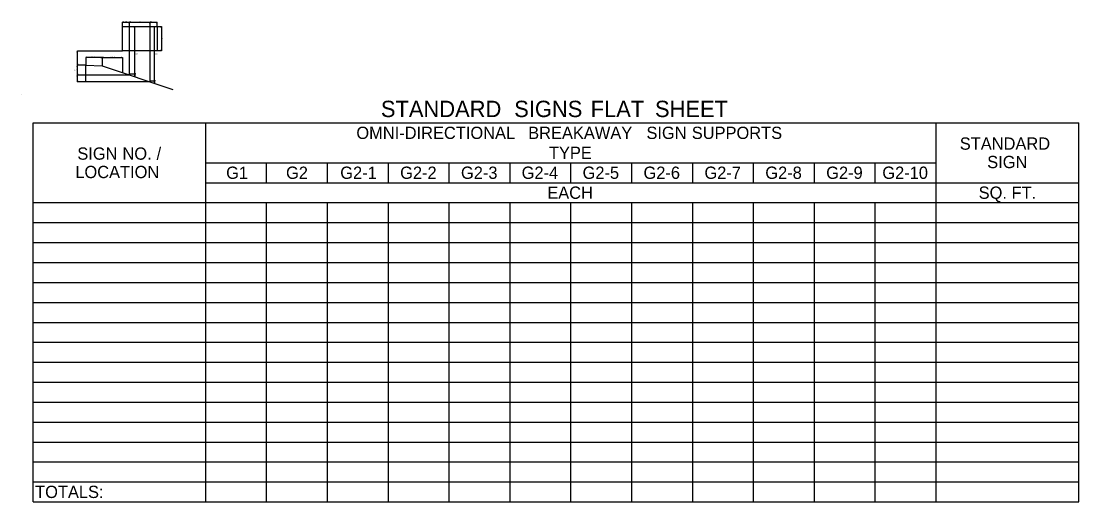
# Model space of a CAD drawing. Extents: x 229 to 4210, y 35 to 1715.
# Drawn here: x 3485 to 4002, y 1480 to 1715 of the extents above; entities that cross this region are included whole.
import ezdxf

# ---------------------------------------------------------------- set-up
doc = ezdxf.new("R2010")
doc.units = 0
for name, color, linetype in [('B_Steel', 7, 'Continuous'), ('B_Steel Hidden', 7, 'Continuous'), ('Default', 7, 'Continuous')]:
    doc.layers.add(name, color=color, linetype=linetype)

msp = doc.modelspace()

# ---------------------------------------------------------------- linework, layer by layer
at = {"layer": 'B_Steel Hidden'}
for p, q in [((3535.51, 1714.6), (3534.91, 1714.51)), ((3534.91, 1712.51), (3534.91, 1714.51)), ((3535.51, 1714.42), (3534.91, 1714.51)), ((3534.91, 1714.51), (3538.29, 1714.51)), ((3535.51, 1714.58), (3535.01, 1714.51)), ((3535.51, 1714.43), (3535.01, 1714.51)), ((3535.51, 1714.57), (3535.11, 1714.51)), ((3535.51, 1714.45), (3535.11, 1714.51)), ((3535.51, 1714.55), (3535.21, 1714.51)), ((3535.51, 1714.46), (3535.21, 1714.51)), ((3535.51, 1714.54), (3535.32, 1714.51)), ((3535.51, 1714.48), (3535.32, 1714.51)), ((3535.51, 1714.52), (3535.42, 1714.51)), ((3535.51, 1714.49), (3535.42, 1714.51)), ((3535.51, 1714.6), (3535.51, 1714.42)), ((3537.69, 1714.6), (3538.29, 1714.51)), ((3537.69, 1714.6), (3537.69, 1714.42)), ((3537.69, 1714.58), (3538.19, 1714.51)), ((3537.69, 1714.57), (3538.09, 1714.51)), ((3537.69, 1714.55), (3537.99, 1714.51)), ((3537.69, 1714.54), (3537.89, 1714.51)), ((3537.69, 1714.52), (3537.79, 1714.51)), ((3537.69, 1714.42), (3538.29, 1714.51)), ((3537.69, 1714.48), (3537.89, 1714.51)), ((3537.69, 1714.45), (3538.09, 1714.51)), ((3537.69, 1714.43), (3538.19, 1714.51)), ((3537.69, 1714.46), (3537.99, 1714.51)), ((3537.69, 1714.49), (3537.79, 1714.51)), ((3538.89, 1714.6), (3538.29, 1714.51)), ((3538.29, 1712.51), (3538.29, 1714.51)), ((3538.89, 1714.42), (3538.29, 1714.51)), ((3538.29, 1714.51), (3548.49, 1714.51)), ((3538.89, 1714.58), (3538.39, 1714.51)), ((3538.89, 1714.43), (3538.39, 1714.51)), ((3538.89, 1714.57), (3538.49, 1714.51)), ((3538.89, 1714.45), (3538.49, 1714.51)), ((3538.89, 1714.55), (3538.59, 1714.51)), ((3538.89, 1714.46), (3538.59, 1714.51)), ((3538.89, 1714.54), (3538.7, 1714.51)), ((3538.89, 1714.48), (3538.7, 1714.51)), ((3538.89, 1714.52), (3538.8, 1714.51)), ((3538.89, 1714.49), (3538.8, 1714.51)), ((3538.89, 1714.6), (3538.89, 1714.42)), ((3540.83, 1711.91), (3540.92, 1712.51)), ((3541.01, 1711.91), (3540.83, 1711.91)), ((3540.85, 1711.91), (3540.92, 1712.41)), ((3540.86, 1711.91), (3540.92, 1712.31)), ((3540.88, 1711.91), (3540.92, 1712.21)), ((3540.89, 1711.91), (3540.92, 1712.1)), ((3540.91, 1711.91), (3540.92, 1712)), ((3540.92, 1689.06), (3540.92, 1712.51)), ((3541.01, 1711.91), (3540.92, 1712.51)), ((3541, 1711.91), (3540.92, 1712.41)), ((3540.98, 1711.91), (3540.92, 1712.31)), ((3540.97, 1711.91), (3540.92, 1712.21)), ((3540.95, 1711.91), (3540.92, 1712.1)), ((3540.94, 1711.91), (3540.92, 1712)), ((3547.89, 1714.6), (3548.49, 1714.51)), ((3547.89, 1714.6), (3547.89, 1714.42)), ((3547.89, 1714.58), (3548.39, 1714.51)), ((3547.89, 1714.57), (3548.29, 1714.51)), ((3547.89, 1714.55), (3548.19, 1714.51)), ((3547.89, 1714.54), (3548.09, 1714.51)), ((3547.89, 1714.52), (3547.99, 1714.51)), ((3547.89, 1714.42), (3548.49, 1714.51)), ((3547.89, 1714.48), (3548.09, 1714.51)), ((3547.89, 1714.45), (3548.29, 1714.51)), ((3547.89, 1714.43), (3548.39, 1714.51)), ((3547.89, 1714.46), (3548.19, 1714.51)), ((3547.89, 1714.49), (3547.99, 1714.51)), ((3549.09, 1714.6), (3548.49, 1714.51)), ((3548.49, 1712.51), (3548.49, 1714.51)), ((3549.09, 1714.42), (3548.49, 1714.51)), ((3548.49, 1714.51), (3551.91, 1714.51)), ((3549.09, 1714.58), (3548.59, 1714.51)), ((3549.09, 1714.43), (3548.59, 1714.51)), ((3549.09, 1714.57), (3548.69, 1714.51)), ((3549.09, 1714.45), (3548.69, 1714.51)), ((3549.09, 1714.55), (3548.79, 1714.51)), ((3549.09, 1714.46), (3548.79, 1714.51)), ((3549.09, 1714.54), (3548.9, 1714.51)), ((3549.09, 1714.48), (3548.9, 1714.51)), ((3549.09, 1714.52), (3549, 1714.51)), ((3549.09, 1714.49), (3549, 1714.51)), ((3549.09, 1714.6), (3549.09, 1714.42)), ((3550.46, 1711.91), (3550.55, 1712.51)), ((3550.64, 1711.91), (3550.46, 1711.91)), ((3550.47, 1711.91), (3550.55, 1712.41)), ((3550.49, 1711.91), (3550.55, 1712.31)), ((3550.5, 1711.91), (3550.55, 1712.21)), ((3550.52, 1711.91), (3550.55, 1712.1)), ((3550.53, 1711.91), (3550.55, 1712)), ((3550.55, 1685.66), (3550.55, 1712.51)), ((3550.64, 1711.91), (3550.55, 1712.51)), ((3550.62, 1711.91), (3550.55, 1712.41)), ((3550.61, 1711.91), (3550.55, 1712.31)), ((3550.59, 1711.91), (3550.55, 1712.21)), ((3550.57, 1711.91), (3550.55, 1712.1)), ((3550.56, 1711.91), (3550.55, 1712)), ((3551.31, 1714.6), (3551.91, 1714.51)), ((3551.31, 1714.6), (3551.31, 1714.42)), ((3551.31, 1714.58), (3551.81, 1714.51)), ((3551.31, 1714.57), (3551.71, 1714.51)), ((3551.31, 1714.55), (3551.61, 1714.51)), ((3551.31, 1714.54), (3551.51, 1714.51)), ((3551.31, 1714.52), (3551.41, 1714.51)), ((3551.31, 1714.42), (3551.91, 1714.51)), ((3551.31, 1714.48), (3551.51, 1714.51)), ((3551.31, 1714.45), (3551.71, 1714.51)), ((3551.31, 1714.43), (3551.81, 1714.51)), ((3551.31, 1714.46), (3551.61, 1714.51)), ((3551.31, 1714.49), (3551.41, 1714.51)), ((3551.91, 1712.51), (3551.91, 1714.51)), ((3551.91, 1712.51), (3553.91, 1712.51)), ((3553.82, 1711.91), (3553.91, 1712.51)), ((3554, 1711.91), (3553.82, 1711.91)), ((3553.84, 1711.91), (3553.91, 1712.41)), ((3553.85, 1711.91), (3553.91, 1712.3)), ((3553.87, 1711.91), (3553.91, 1712.2)), ((3553.88, 1711.91), (3553.91, 1712.1)), ((3553.9, 1711.91), (3553.91, 1712)), ((3553.91, 1712.51), (3553.91, 1700.51)), ((3554, 1711.91), (3553.91, 1712.51)), ((3553.99, 1711.91), (3553.91, 1712.41)), ((3553.97, 1711.91), (3553.91, 1712.3)), ((3553.96, 1711.91), (3553.91, 1712.2)), ((3553.94, 1711.91), (3553.91, 1712.1)), ((3553.93, 1711.91), (3553.91, 1712)), ((3512.75, 1699.91), (3512.84, 1700.51)), ((3512.76, 1699.91), (3512.84, 1700.41)), ((3512.78, 1699.91), (3512.84, 1700.3)), ((3512.79, 1699.91), (3512.84, 1700.2)), ((3512.84, 1693.51), (3512.84, 1700.51)), ((3512.93, 1699.91), (3512.84, 1700.51)), ((3512.84, 1700.51), (3534.91, 1700.51)), ((3512.91, 1699.91), (3512.84, 1700.41)), ((3512.9, 1699.91), (3512.84, 1700.3)), ((3512.88, 1699.91), (3512.84, 1700.2)), ((3553.91, 1700.51), (3551.91, 1700.51)), ((3553.82, 1701.11), (3553.91, 1700.51)), ((3553.82, 1701.11), (3554, 1701.11)), ((3553.84, 1701.11), (3553.91, 1700.61)), ((3553.85, 1701.11), (3553.91, 1700.71)), ((3553.87, 1701.11), (3553.91, 1700.81)), ((3553.88, 1701.11), (3553.91, 1700.91)), ((3553.9, 1701.11), (3553.91, 1701.01)), ((3554, 1701.11), (3553.91, 1700.51)), ((3553.94, 1701.11), (3553.91, 1700.91)), ((3553.97, 1701.11), (3553.91, 1700.71)), ((3553.99, 1701.11), (3553.91, 1700.61)), ((3553.96, 1701.11), (3553.91, 1700.81)), ((3553.93, 1701.11), (3553.91, 1701.01)), ((3512.93, 1699.91), (3512.75, 1699.91)), ((3512.81, 1699.91), (3512.84, 1700.1)), ((3512.82, 1699.91), (3512.84, 1700)), ((3512.87, 1699.91), (3512.84, 1700.1)), ((3512.85, 1699.91), (3512.84, 1700)), ((3517.51, 1697.4), (3516.91, 1697.31)), ((3517.51, 1697.22), (3516.91, 1697.31)), ((3516.91, 1697.31), (3516.91, 1693.51)), ((3524.91, 1697.31), (3516.91, 1697.31)), ((3517.51, 1697.38), (3517.01, 1697.31)), ((3517.51, 1697.23), (3517.01, 1697.31)), ((3517.51, 1697.37), (3517.11, 1697.31)), ((3517.51, 1697.25), (3517.11, 1697.31)), ((3517.51, 1697.35), (3517.21, 1697.31)), ((3517.51, 1697.26), (3517.21, 1697.31)), ((3517.51, 1697.34), (3517.32, 1697.31)), ((3517.51, 1697.28), (3517.32, 1697.31)), ((3517.51, 1697.32), (3517.42, 1697.31)), ((3517.51, 1697.29), (3517.42, 1697.31)), ((3517.51, 1697.4), (3517.51, 1697.22)), ((3524.31, 1697.4), (3524.91, 1697.31)), ((3524.31, 1697.4), (3524.31, 1697.22)), ((3524.31, 1697.38), (3524.81, 1697.31)), ((3524.31, 1697.37), (3524.71, 1697.31)), ((3524.31, 1697.35), (3524.61, 1697.31)), ((3524.31, 1697.34), (3524.51, 1697.31)), ((3524.31, 1697.32), (3524.41, 1697.31)), ((3524.31, 1697.22), (3524.91, 1697.31)), ((3524.31, 1697.28), (3524.51, 1697.31)), ((3524.31, 1697.25), (3524.71, 1697.31)), ((3524.31, 1697.23), (3524.81, 1697.31)), ((3524.31, 1697.26), (3524.61, 1697.31)), ((3524.31, 1697.29), (3524.41, 1697.31)), ((3525.51, 1697.4), (3524.91, 1697.31)), ((3524.91, 1697.31), (3524.91, 1693.19)), ((3525.51, 1697.22), (3524.91, 1697.31)), ((3524.91, 1697.31), (3534.91, 1697.31)), ((3525.51, 1697.38), (3525.01, 1697.31)), ((3525.51, 1697.23), (3525.01, 1697.31)), ((3525.51, 1697.37), (3525.11, 1697.31)), ((3525.51, 1697.25), (3525.11, 1697.31)), ((3525.51, 1697.35), (3525.21, 1697.31)), ((3525.51, 1697.26), (3525.21, 1697.31)), ((3525.51, 1697.34), (3525.32, 1697.31)), ((3525.51, 1697.28), (3525.32, 1697.31)), ((3525.51, 1697.32), (3525.42, 1697.31)), ((3525.51, 1697.29), (3525.42, 1697.31)), ((3525.51, 1697.4), (3525.51, 1697.22)), ((3534.31, 1697.4), (3534.91, 1697.31)), ((3534.31, 1697.4), (3534.31, 1697.22)), ((3534.31, 1697.38), (3534.81, 1697.31)), ((3534.31, 1697.37), (3534.71, 1697.31)), ((3534.31, 1697.35), (3534.61, 1697.31)), ((3534.31, 1697.34), (3534.51, 1697.31)), ((3534.31, 1697.32), (3534.41, 1697.31)), ((3534.31, 1697.22), (3534.91, 1697.31)), ((3534.31, 1697.28), (3534.51, 1697.31)), ((3534.31, 1697.25), (3534.71, 1697.31)), ((3534.31, 1697.23), (3534.81, 1697.31)), ((3534.31, 1697.26), (3534.61, 1697.31)), ((3534.31, 1697.29), (3534.41, 1697.31)), ((3534.91, 1697.31), (3534.91, 1689.85)), ((3512.75, 1694.11), (3512.84, 1693.51)), ((3512.75, 1694.11), (3512.93, 1694.11)), ((3512.75, 1692.91), (3512.84, 1693.51)), ((3512.93, 1692.91), (3512.75, 1692.91)), ((3512.76, 1694.11), (3512.84, 1693.61)), ((3512.76, 1692.91), (3512.84, 1693.41)), ((3512.78, 1694.11), (3512.84, 1693.71)), ((3512.78, 1692.91), (3512.84, 1693.3)), ((3512.79, 1694.11), (3512.84, 1693.81)), ((3512.79, 1692.91), (3512.84, 1693.2)), ((3512.81, 1694.11), (3512.84, 1693.91)), ((3512.81, 1692.91), (3512.84, 1693.1)), ((3512.82, 1694.11), (3512.84, 1694.01)), ((3512.82, 1692.91), (3512.84, 1693)), ((3512.93, 1694.11), (3512.84, 1693.51)), ((3512.87, 1694.11), (3512.84, 1693.91)), ((3512.9, 1694.11), (3512.84, 1693.71)), ((3512.91, 1694.11), (3512.84, 1693.61)), ((3512.88, 1694.11), (3512.84, 1693.81)), ((3512.85, 1694.11), (3512.84, 1694.01)), ((3512.84, 1688.73), (3512.84, 1693.51)), ((3512.93, 1692.91), (3512.84, 1693.51)), ((3512.91, 1692.91), (3512.84, 1693.41)), ((3512.9, 1692.91), (3512.84, 1693.3)), ((3512.88, 1692.91), (3512.84, 1693.2)), ((3512.87, 1692.91), (3512.84, 1693.1)), ((3512.85, 1692.91), (3512.84, 1693)), ((3512.75, 1689.33), (3512.84, 1688.73)), ((3512.75, 1689.33), (3512.93, 1689.33)), ((3512.75, 1688.13), (3512.84, 1688.73)), ((3512.93, 1688.13), (3512.75, 1688.13)), ((3512.75, 1685.93), (3512.84, 1685.33)), ((3512.75, 1685.93), (3512.93, 1685.93)), ((3512.76, 1689.33), (3512.84, 1688.83)), ((3512.76, 1688.13), (3512.84, 1688.63)), ((3512.76, 1685.93), (3512.84, 1685.43)), ((3512.78, 1689.33), (3512.84, 1688.93)), ((3512.78, 1688.13), (3512.84, 1688.52)), ((3512.78, 1685.93), (3512.84, 1685.53)), ((3512.79, 1689.33), (3512.84, 1689.03)), ((3512.79, 1688.13), (3512.84, 1688.42)), ((3512.79, 1685.93), (3512.84, 1685.63)), ((3512.81, 1689.33), (3512.84, 1689.13)), ((3512.81, 1688.13), (3512.84, 1688.32)), ((3512.81, 1685.93), (3512.84, 1685.73)), ((3512.82, 1689.33), (3512.84, 1689.23)), ((3512.82, 1688.13), (3512.84, 1688.22)), ((3512.82, 1685.93), (3512.84, 1685.83)), ((3512.93, 1689.33), (3512.84, 1688.73)), ((3512.87, 1689.33), (3512.84, 1689.13)), ((3512.9, 1689.33), (3512.84, 1688.93)), ((3512.91, 1689.33), (3512.84, 1688.83)), ((3512.88, 1689.33), (3512.84, 1689.03)), ((3512.85, 1689.33), (3512.84, 1689.23)), ((3512.84, 1685.33), (3512.84, 1688.73)), ((3512.93, 1688.13), (3512.84, 1688.73)), ((3512.91, 1688.13), (3512.84, 1688.63)), ((3512.9, 1688.13), (3512.84, 1688.52)), ((3512.88, 1688.13), (3512.84, 1688.42)), ((3512.87, 1688.13), (3512.84, 1688.32)), ((3512.85, 1688.13), (3512.84, 1688.22)), ((3512.93, 1685.93), (3512.84, 1685.33)), ((3512.87, 1685.93), (3512.84, 1685.73)), ((3512.9, 1685.93), (3512.84, 1685.53)), ((3512.91, 1685.93), (3512.84, 1685.43)), ((3512.88, 1685.93), (3512.84, 1685.63)), ((3512.85, 1685.93), (3512.84, 1685.83)), ((3540.92, 1689.06), (3538.29, 1689.06)), ((3540.83, 1689.66), (3540.92, 1689.06)), ((3540.83, 1689.66), (3541.01, 1689.66)), ((3540.83, 1688.13), (3540.92, 1688.73)), ((3541.01, 1688.13), (3540.83, 1688.13)), ((3540.85, 1689.66), (3540.92, 1689.16)), ((3540.85, 1688.13), (3540.92, 1688.63)), ((3540.86, 1689.66), (3540.92, 1689.26)), ((3540.86, 1688.13), (3540.92, 1688.52)), ((3540.88, 1689.66), (3540.92, 1689.36)), ((3540.88, 1688.13), (3540.92, 1688.42)), ((3540.89, 1689.66), (3540.92, 1689.46)), ((3540.89, 1688.13), (3540.92, 1688.32)), ((3540.91, 1689.66), (3540.92, 1689.56)), ((3540.91, 1688.13), (3540.92, 1688.22)), ((3541.01, 1689.66), (3540.92, 1689.06)), ((3540.95, 1689.66), (3540.92, 1689.46)), ((3540.98, 1689.66), (3540.92, 1689.26)), ((3541, 1689.66), (3540.92, 1689.16)), ((3540.97, 1689.66), (3540.92, 1689.36)), ((3540.94, 1689.66), (3540.92, 1689.56)), ((3540.92, 1689.06), (3540.92, 1688.73)), ((3541.01, 1688.13), (3540.92, 1688.73)), ((3540.92, 1688.73), (3540.92, 1687.73)), ((3541, 1688.13), (3540.92, 1688.63)), ((3540.98, 1688.13), (3540.92, 1688.52)), ((3540.97, 1688.13), (3540.92, 1688.42)), ((3540.95, 1688.13), (3540.92, 1688.32)), ((3540.94, 1688.13), (3540.92, 1688.22)), ((3550.55, 1685.66), (3548.49, 1685.66)), ((3550.46, 1686.26), (3550.55, 1685.66)), ((3550.46, 1686.26), (3550.64, 1686.26)), ((3550.46, 1684.73), (3550.55, 1685.33)), ((3550.64, 1684.73), (3550.46, 1684.73)), ((3550.47, 1686.26), (3550.55, 1685.76)), ((3550.47, 1684.73), (3550.55, 1685.23)), ((3550.49, 1686.26), (3550.55, 1685.86)), ((3550.49, 1684.73), (3550.55, 1685.12)), ((3550.5, 1686.26), (3550.55, 1685.96)), ((3550.5, 1684.73), (3550.55, 1685.02)), ((3550.52, 1686.26), (3550.55, 1686.06)), ((3550.52, 1684.73), (3550.55, 1684.92)), ((3550.53, 1686.26), (3550.55, 1686.16)), ((3550.53, 1684.73), (3550.55, 1684.82)), ((3550.64, 1686.26), (3550.55, 1685.66)), ((3550.57, 1686.26), (3550.55, 1686.06)), ((3550.61, 1686.26), (3550.55, 1685.86)), ((3550.62, 1686.26), (3550.55, 1685.76)), ((3550.59, 1686.26), (3550.55, 1685.96)), ((3550.56, 1686.26), (3550.55, 1686.16)), ((3550.55, 1685.66), (3550.55, 1685.33)), ((3550.64, 1684.73), (3550.55, 1685.33)), ((3550.55, 1685.33), (3550.55, 1684.33)), ((3550.62, 1684.73), (3550.55, 1685.23)), ((3550.61, 1684.73), (3550.55, 1685.12)), ((3550.59, 1684.73), (3550.55, 1685.02)), ((3550.57, 1684.73), (3550.55, 1684.92)), ((3550.56, 1684.73), (3550.55, 1684.82))]:
    msp.add_line(p, q, dxfattribs=at)
at = {"layer": 'Default'}
for p, q in [((3534.91, 1700.51), (3534.91, 1712.51)), ((3534.91, 1712.51), (3551.91, 1712.51)), ((3538.29, 1689.06), (3538.29, 1712.51)), ((3548.49, 1685.66), (3548.49, 1712.51)), ((3551.91, 1712.51), (3551.91, 1700.51)), ((3538.31, 1700.51), (3534.91, 1700.51)), ((3548.51, 1700.51), (3538.31, 1700.51)), ((3551.91, 1700.51), (3548.51, 1700.51)), ((3516.91, 1693.51), (3512.84, 1693.51)), ((3516.91, 1688.73), (3516.91, 1693.51)), ((3516.91, 1693.51), (3524.91, 1693.19)), ((3524.91, 1693.19), (3559.45, 1681.67)), ((3512.84, 1688.73), (3538.29, 1688.73)), ((3548.49, 1685.33), (3512.84, 1685.33)), ((3516.91, 1685.33), (3516.91, 1688.73)), ((3538.29, 1688.73), (3538.29, 1689.06)), ((3548.49, 1685.33), (3548.49, 1685.66)), ((3485.38, 1678.97), (3485.38, 1678.97)), ((3491.23, 1665.32), (4002.13, 1665.32)), ((3491.23, 1480.07), (3491.23, 1665.32)), ((3491.23, 1480.07), (3491.23, 1665.32)), ((3575.57, 1480.07), (3575.57, 1665.32)), ((3932.42, 1480.07), (3932.42, 1665.32)), ((4002.13, 1480.07), (4002.13, 1665.32)), ((3575.57, 1645.82), (3932.42, 1645.82)), ((3605.3, 1636.07), (3605.3, 1645.82)), ((3635.04, 1636.07), (3635.04, 1645.82)), ((3664.78, 1636.07), (3664.78, 1645.82)), ((3694.52, 1636.07), (3694.52, 1645.82)), ((3724.25, 1636.07), (3724.25, 1645.82)), ((3753.99, 1636.07), (3753.99, 1645.82)), ((3783.73, 1636.07), (3783.73, 1645.82)), ((3813.47, 1636.07), (3813.47, 1645.82)), ((3843.2, 1636.07), (3843.2, 1645.82)), ((3872.94, 1636.07), (3872.94, 1645.82)), ((3902.68, 1636.07), (3902.68, 1645.82)), ((3575.57, 1636.07), (4002.13, 1636.07)), ((3575.57, 1636.07), (3902.68, 1636.07)), ((3491.23, 1626.32), (4002.13, 1626.32)), ((3575.57, 1480.07), (3575.57, 1626.32)), ((3605.3, 1489.82), (3605.3, 1626.32)), ((3605.3, 1480.07), (3605.3, 1626.32)), ((3635.04, 1489.82), (3635.04, 1626.32)), ((3635.04, 1480.07), (3635.04, 1626.32)), ((3664.78, 1489.82), (3664.78, 1626.32)), ((3664.78, 1480.07), (3664.78, 1626.32)), ((3694.52, 1489.82), (3694.52, 1626.32)), ((3694.52, 1480.07), (3694.52, 1626.32)), ((3724.25, 1489.82), (3724.25, 1626.32)), ((3724.25, 1480.07), (3724.25, 1626.32)), ((3753.99, 1489.82), (3753.99, 1626.32)), ((3753.99, 1480.07), (3753.99, 1626.32)), ((3783.73, 1489.82), (3783.73, 1626.32)), ((3783.73, 1480.07), (3783.73, 1626.32)), ((3813.47, 1489.82), (3813.47, 1626.32)), ((3813.47, 1480.07), (3813.47, 1626.32)), ((3843.2, 1489.82), (3843.2, 1626.32)), ((3843.2, 1480.07), (3843.2, 1626.32)), ((3872.94, 1489.82), (3872.94, 1626.32)), ((3872.94, 1480.07), (3872.94, 1626.32)), ((3902.68, 1489.82), (3902.68, 1626.32)), ((3902.68, 1480.07), (3902.68, 1626.32)), ((3932.42, 1626.32), (4002.13, 1626.32)), ((3932.42, 1489.82), (3932.42, 1626.32)), ((3491.23, 1616.57), (4002.13, 1616.57)), ((3491.23, 1606.82), (4002.13, 1606.82)), ((3491.23, 1597.07), (4002.13, 1597.07)), ((3491.23, 1587.32), (4002.13, 1587.32)), ((3491.23, 1577.57), (4002.13, 1577.57)), ((3491.23, 1567.82), (4002.13, 1567.82)), ((3491.23, 1558.07), (4002.13, 1558.07)), ((3491.23, 1548.32), (4002.13, 1548.32)), ((3491.23, 1538.57), (4002.13, 1538.57)), ((3491.23, 1528.82), (4002.13, 1528.82)), ((3491.23, 1519.07), (4002.13, 1519.07)), ((3491.23, 1509.32), (4002.13, 1509.32)), ((3491.23, 1499.57), (4002.13, 1499.57)), ((3491.23, 1489.82), (4002.13, 1489.82)), ((4002.13, 1480.07), (4002.13, 1489.82)), ((3491.23, 1480.07), (4002.13, 1480.07))]:
    msp.add_line(p, q, dxfattribs=at)

# ---------------------------------------------------------------- texts
at = {"layer": 'B_Steel'}
for s, p in [("3.4'", (3536.09, 1714.69)), ("10.2'", (3542.79, 1714.69)), ("3.4'", (3549.67, 1714.69)), ("12'", (3554.09, 1706.33)), ("7'", (3512.15, 1696.83)), ("8' @ 4%", (3519.85, 1697.49)), ("10' @ 3:1", (3528.81, 1697.49)), ("23.45'", (3541.1, 1698.9)), ("26.85'", (3550.73, 1698.9)), ("4.78'", (3511.23, 1690.94)), ("3.4'", (3511.59, 1687.05)), ('4"', (3541.1, 1688.71)), ('4"', (3550.73, 1685.31))]:
    msp.add_text(s, height=0.36, dxfattribs=at).set_placement(p)
at = {"layer": 'Default'}
for s, height, p in [('STANDARD', 8, (3661.13, 1668.15)), (' SIGNS', 8, (3723.3, 1668.15)), (' FLAT', 8, (3760.65, 1668.15)), (' SHEET', 8, (3792.08, 1668.15)), ('OMNI-DIRECTIONAL', 6, (3649.15, 1657.45)), (' BREAKAWAY', 6, (3730.87, 1657.45)), (' SIGN', 6, (3788.64, 1657.45)), (' SUPPORTS', 6, (3810.79, 1657.45)), (' /', 6, (3549.31, 1647.32)), ('TYPE', 6, (3743.25, 1647.7)), ('STANDARD', 6, (3943.96, 1652.2)), ('SIGN', 6, (3512.83, 1647.32)), (' NO.', 6, (3532.65, 1647.32)), ('SIGN', 6, (3957.36, 1643.2)), ('LOCATION', 6, (3511.84, 1638.32)), ('G1', 6, (3585.52, 1637.95)), ('G2', 6, (3614.79, 1637.95)), ('G2-1', 6, (3641.27, 1637.95)), ('G2-2', 6, (3670.54, 1637.95)), ('G2-3', 6, (3700.25, 1637.95)), ('G2-4', 6, (3729.9, 1637.95)), ('G2-5', 6, (3759.67, 1637.95)), ('G2-6', 6, (3789.43, 1637.95)), ('G2-7', 6, (3819.2, 1637.95)), ('G2-8', 6, (3848.94, 1637.95)), ('G2-9', 6, (3878.69, 1637.95)), ('G2-10', 6, (3906.11, 1637.95)), ('EACH', 6, (3742.43, 1628.2)), ('SQ.', 6, (3953.18, 1628.2)), (' FT.', 6, (3967.04, 1628.2)), ('TOTALS:', 6, (3492.2, 1481.95))]:
    msp.add_text(s, height=height, dxfattribs=at).set_placement(p)

doc.saveas('drawing.dxf')
